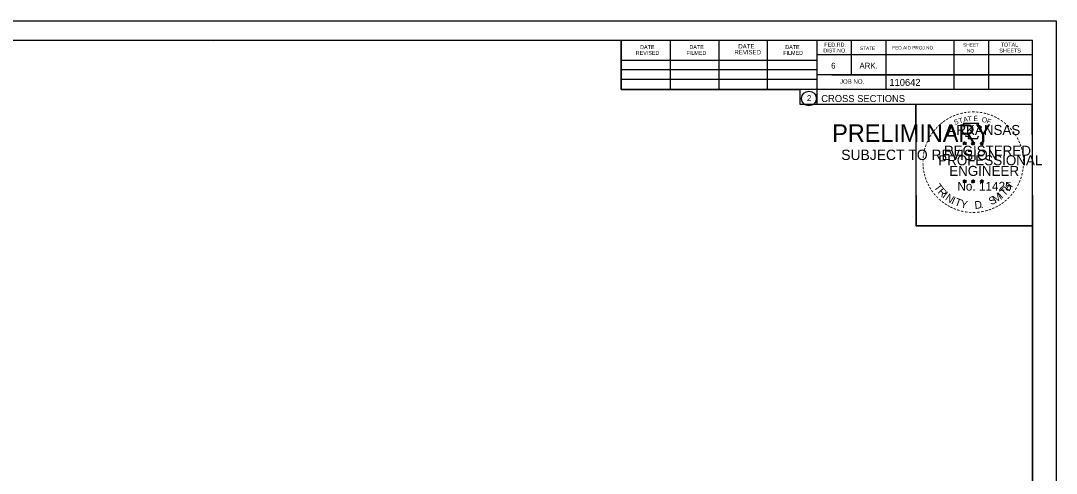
# Model space of a CAD drawing. Extents: x 1368503 to 1373085, y 379840 to 381833.
# Drawn here: x 1368628.9 to 1368836, y 380888.9 to 380979.4 of the extents above; entities that cross this region are included whole.
import ezdxf

# ---------------------------------------------------------------- set-up
doc = ezdxf.new("R2010")
doc.units = 0
for name, color, linetype in [('S_BRIDGE', 7, 'Continuous'), ('S_LANDSCAPING', 7, 'Continuous'), ('S_MISC_BOUNDARY_ANNOT', 7, 'Continuous'), ('S_PHOTO_NOTES', 7, 'Continuous')]:
    doc.layers.add(name, color=color, linetype=linetype)

msp = doc.modelspace()

# ---------------------------------------------------------------- linework, layer by layer
at = {"layer": 'S_BRIDGE'}
for p, q in [((1368515.06, 380975.5), (1368831.24, 380975.5)), ((1368667.58, 380975.24), (1368667.58, 380975.24)), ((1368667.58, 380975.24), (1368667.58, 380975.24)), ((1368748.98, 380965.62), (1368748.98, 380975.5)), ((1368758.84, 380965.62), (1368758.84, 380975.3)), ((1368768.6, 380965.62), (1368768.6, 380975.3)), ((1368778.28, 380965.62), (1368778.28, 380975.3)), ((1368788.14, 380975.5), (1368788.14, 380962.7)), ((1368794.98, 380975.5), (1368794.98, 380968.56)), ((1368801.92, 380975.5), (1368801.92, 380965.62)), ((1368815.5, 380975.5), (1368815.5, 380965.62)), ((1368822.44, 380975.5), (1368822.44, 380965.62)), ((1368831.24, 380770.04), (1368831.24, 380975.5)), ((1368831.24, 380972.56), (1368788.14, 380972.56)), ((1368831.24, 380972.58), (1368831.24, 380972.58)), ((1368748.98, 380971.48), (1368788.14, 380971.48)), ((1368748.98, 380969.62), (1368788.14, 380969.62)), ((1368748.98, 380965.62), (1368748.98, 380967.68)), ((1368748.98, 380967.68), (1368788.14, 380967.68)), ((1368831.24, 380968.56), (1368788.14, 380968.56)), ((1368791.1, 380968.56), (1368831.24, 380968.56)), ((1368831.24, 380965.62), (1368748.98, 380965.62)), ((1368788.14, 380962.7), (1368831.24, 380962.7))]:
    msp.add_line(p, q, dxfattribs=at)
msp.add_circle((1368786.53, 380963.84), 1.47, dxfattribs=at)
at = {"layer": 'S_LANDSCAPING'}
for p, q in [((1368817.67, 380955.21), (1368817.63, 380954.96)), ((1368817.67, 380954.85), (1368817.67, 380955.21)), ((1368817.67, 380955.21), (1368817.72, 380954.96)), ((1368819.34, 380955.21), (1368819.3, 380954.96)), ((1368819.34, 380954.85), (1368819.34, 380955.21)), ((1368819.34, 380955.21), (1368819.39, 380954.96)), ((1368821.11, 380955.2), (1368821.07, 380954.95)), ((1368821.11, 380954.83), (1368821.11, 380955.2)), ((1368821.11, 380955.2), (1368821.16, 380954.95)), ((1368817.32, 380954.96), (1368817.67, 380954.85)), ((1368817.32, 380954.96), (1368817.58, 380954.91)), ((1368817.32, 380954.96), (1368817.56, 380954.84)), ((1368817.46, 380954.55), (1368817.67, 380954.85)), ((1368817.46, 380954.55), (1368817.58, 380954.79)), ((1368817.46, 380954.55), (1368817.67, 380954.77)), ((1368818.02, 380954.96), (1368817.67, 380954.85)), ((1368817.89, 380954.55), (1368817.67, 380954.85)), ((1368817.89, 380954.55), (1368817.67, 380954.76)), ((1368818.02, 380954.96), (1368817.73, 380954.91)), ((1368817.89, 380954.55), (1368817.75, 380954.84)), ((1368818.02, 380954.96), (1368817.82, 380954.86)), ((1368818.99, 380954.96), (1368819.34, 380954.85)), ((1368818.99, 380954.96), (1368819.25, 380954.91)), ((1368818.99, 380954.96), (1368819.23, 380954.84)), ((1368819.13, 380954.55), (1368819.34, 380954.85)), ((1368819.13, 380954.55), (1368819.25, 380954.79)), ((1368819.13, 380954.55), (1368819.34, 380954.77)), ((1368819.69, 380954.96), (1368819.34, 380954.85)), ((1368819.56, 380954.55), (1368819.34, 380954.85)), ((1368819.56, 380954.55), (1368819.34, 380954.76)), ((1368819.69, 380954.96), (1368819.4, 380954.91)), ((1368819.56, 380954.55), (1368819.42, 380954.84)), ((1368819.69, 380954.96), (1368819.49, 380954.86)), ((1368820.76, 380954.95), (1368821.11, 380954.83)), ((1368820.76, 380954.95), (1368821.01, 380954.9)), ((1368820.76, 380954.95), (1368820.99, 380954.82)), ((1368820.89, 380954.54), (1368821.11, 380954.83)), ((1368820.89, 380954.54), (1368821.02, 380954.78)), ((1368820.89, 380954.54), (1368821.1, 380954.75)), ((1368821.32, 380954.54), (1368821.1, 380954.75)), ((1368821.45, 380954.95), (1368821.11, 380954.83)), ((1368821.32, 380954.54), (1368821.11, 380954.83)), ((1368821.45, 380954.95), (1368821.17, 380954.9)), ((1368821.32, 380954.54), (1368821.18, 380954.83)), ((1368821.45, 380954.95), (1368821.25, 380954.84)), ((1368817.32, 380947.38), (1368817.67, 380947.27)), ((1368817.32, 380947.38), (1368817.57, 380947.34)), ((1368817.32, 380947.38), (1368817.56, 380947.26)), ((1368817.45, 380946.98), (1368817.67, 380947.27)), ((1368817.45, 380946.98), (1368817.58, 380947.22)), ((1368817.45, 380946.98), (1368817.67, 380947.19)), ((1368817.67, 380947.64), (1368817.63, 380947.39)), ((1368817.67, 380947.27), (1368817.67, 380947.64)), ((1368817.67, 380947.64), (1368817.72, 380947.39)), ((1368818.02, 380947.38), (1368817.67, 380947.27)), ((1368817.88, 380946.98), (1368817.67, 380947.27)), ((1368817.88, 380946.98), (1368817.67, 380947.19)), ((1368818.02, 380947.38), (1368817.73, 380947.34)), ((1368817.88, 380946.98), (1368817.74, 380947.27)), ((1368818.02, 380947.38), (1368817.81, 380947.28)), ((1368818.99, 380947.38), (1368819.34, 380947.27)), ((1368818.99, 380947.38), (1368819.24, 380947.34)), ((1368818.99, 380947.38), (1368819.23, 380947.26)), ((1368819.12, 380946.98), (1368819.34, 380947.27)), ((1368819.12, 380946.98), (1368819.25, 380947.22)), ((1368819.12, 380946.98), (1368819.34, 380947.19)), ((1368819.34, 380947.64), (1368819.3, 380947.39)), ((1368819.34, 380947.27), (1368819.34, 380947.64)), ((1368819.34, 380947.64), (1368819.39, 380947.39)), ((1368819.68, 380947.38), (1368819.34, 380947.27)), ((1368819.55, 380946.98), (1368819.34, 380947.27)), ((1368819.55, 380946.98), (1368819.34, 380947.19)), ((1368819.68, 380947.38), (1368819.4, 380947.34)), ((1368819.55, 380946.98), (1368819.41, 380947.27)), ((1368819.68, 380947.38), (1368819.48, 380947.28)), ((1368820.76, 380947.37), (1368821.1, 380947.26)), ((1368820.76, 380947.37), (1368821.01, 380947.33)), ((1368820.76, 380947.37), (1368820.99, 380947.25)), ((1368820.89, 380946.97), (1368821.1, 380947.26)), ((1368820.89, 380946.97), (1368821.01, 380947.21)), ((1368820.89, 380946.97), (1368821.1, 380947.18)), ((1368821.1, 380947.63), (1368821.06, 380947.38)), ((1368821.1, 380947.26), (1368821.1, 380947.63)), ((1368821.1, 380947.63), (1368821.15, 380947.38)), ((1368821.45, 380947.37), (1368821.1, 380947.26)), ((1368821.32, 380946.97), (1368821.1, 380947.26)), ((1368821.32, 380946.97), (1368821.1, 380947.18)), ((1368821.45, 380947.37), (1368821.17, 380947.33)), ((1368821.32, 380946.97), (1368821.18, 380947.26)), ((1368821.45, 380947.37), (1368821.25, 380947.27))]:
    msp.add_line(p, q, dxfattribs=at)
for points in [[(1368817.36, 380958.84), (1368817.63, 380958.01)], [(1368820.88, 380957.91), (1368821.02, 380958.2), (1368820.33, 380958.17), (1368820.48, 380958.84), (1368817.36, 380958.84)], [(1368817.67, 380955.21), (1368817.89, 380954.55), (1368817.32, 380954.96), (1368818.02, 380954.96), (1368817.46, 380954.55), (1368817.67, 380955.21)], [(1368817.86, 380956.41), (1368817.86, 380956.33), (1368818.42, 380956.31), (1368818.37, 380955.83), (1368820.24, 380955.83), (1368820.44, 380956.37)], [(1368819.34, 380955.21), (1368819.56, 380954.55), (1368818.99, 380954.96), (1368819.69, 380954.96), (1368819.13, 380954.55), (1368819.34, 380955.21)], [(1368821.11, 380955.2), (1368821.32, 380954.54), (1368820.76, 380954.95), (1368821.45, 380954.95), (1368820.89, 380954.54), (1368821.11, 380955.2)], [(1368817.67, 380947.64), (1368817.88, 380946.98), (1368817.32, 380947.38), (1368818.02, 380947.38), (1368817.45, 380946.98), (1368817.67, 380947.64)], [(1368819.34, 380947.64), (1368819.55, 380946.98), (1368818.99, 380947.38), (1368819.68, 380947.38), (1368819.12, 380946.98), (1368819.34, 380947.64)], [(1368821.1, 380947.63), (1368821.32, 380946.97), (1368820.76, 380947.37), (1368821.45, 380947.37), (1368820.89, 380946.97), (1368821.1, 380947.63)]]:
    msp.add_lwpolyline(points, dxfattribs=at)
for centre, radius in [((1368817.67, 380954.85), 0.172), ((1368817.67, 380954.85), 0.145), ((1368817.67, 380954.85), 0.116), ((1368817.67, 380954.85), 0.0991), ((1368817.67, 380954.85), 0.0747), ((1368817.67, 380954.85), 0.0495), ((1368817.67, 380954.85), 0.0296), ((1368819.34, 380954.85), 0.172), ((1368819.34, 380954.85), 0.145), ((1368819.34, 380954.85), 0.116), ((1368819.34, 380954.85), 0.0991), ((1368819.34, 380954.85), 0.0747), ((1368819.34, 380954.85), 0.0495), ((1368819.34, 380954.85), 0.0296), ((1368821.11, 380954.83), 0.172), ((1368821.11, 380954.83), 0.145), ((1368821.11, 380954.83), 0.116), ((1368821.11, 380954.83), 0.0991), ((1368821.11, 380954.83), 0.0747), ((1368821.11, 380954.83), 0.0495), ((1368821.11, 380954.83), 0.0296), ((1368817.67, 380947.27), 0.172), ((1368817.67, 380947.27), 0.145), ((1368817.67, 380947.27), 0.116), ((1368817.67, 380947.27), 0.0991), ((1368817.67, 380947.27), 0.0747), ((1368817.67, 380947.27), 0.0495), ((1368817.67, 380947.27), 0.0296), ((1368819.34, 380947.27), 0.172), ((1368819.34, 380947.27), 0.145), ((1368819.34, 380947.27), 0.116), ((1368819.34, 380947.27), 0.0991), ((1368819.34, 380947.27), 0.0747), ((1368819.34, 380947.27), 0.0495), ((1368819.34, 380947.27), 0.0296), ((1368821.1, 380947.26), 0.172), ((1368821.1, 380947.26), 0.145), ((1368821.1, 380947.26), 0.116), ((1368821.1, 380947.26), 0.0991), ((1368821.1, 380947.26), 0.0747), ((1368821.1, 380947.26), 0.0495), ((1368821.1, 380947.26), 0.0296)]:
    msp.add_circle(centre, radius, dxfattribs=at)
at = {"layer": 'S_PHOTO_NOTES'}
for p, q in [((1368502.66, 380979.4), (1368835.99, 380979.4)), ((1368807.27, 380940.25), (1368807.27, 380940.25))]:
    msp.add_line(p, q, dxfattribs=at)
for points in [[(1368502.65, 380979.4), (1368835.99, 380979.4), (1368835.99, 380766.06), (1368502.65, 380766.06)], [(1368748.98, 380975.5), (1368748.98, 380965.62), (1368784.71, 380965.62), (1368784.71, 380962.7), (1368807.91, 380962.7), (1368807.91, 380938.37), (1368831.24, 380938.37), (1368831.24, 380770.04), (1368515.06, 380770.04), (1368515.06, 380975.5)], [(1368807.91, 380962.7), (1368831.12, 380962.7), (1368831.24, 380938.37), (1368808.03, 380938.37)]]:
    msp.add_lwpolyline(points, close=True, dxfattribs=at)

# ---------------------------------------------------------------- texts
at = {"layer": 'S_BRIDGE'}
for s, height, p in [('DATE', 0.782, (1368752.78, 380973.74)), ('DATE', 0.782, (1368762.64, 380973.74)), ('DATE', 0.879, (1368772.42, 380973.84)), ('DATE', 0.782, (1368781.8, 380973.74)), ('DIST.NO.', 0.782, (1368789.42, 380973.04)), ('FED.RD.', 0.782, (1368789.62, 380974.22)), ('STATE', 0.684, (1368796.74, 380973.54)), ('FED.AID PROJ.NO.', 0.684, (1368803.2, 380973.64)), ('SHEET', 0.684, (1368817.36, 380974.22)), ('NO.', 0.684, (1368818.14, 380973.04)), ('SHEETS', 0.782, (1368824.6, 380973.04)), ('TOTAL', 0.782, (1368824.88, 380974.22)), ('REVISED', 0.782, (1368751.9, 380972.56)), ('FILMED', 0.782, (1368762.06, 380972.56)), ('REVISED', 0.879, (1368771.64, 380972.66)), ('FILMED', 0.782, (1368781.4, 380972.56)), ('6', 1.17, (1368790.98, 380969.82)), ('ARK.', 1.172, (1368796.64, 380969.82)), ('JOB NO.', 0.879, (1368792.74, 380966.8)), ('110642', 1.4, (1368802.61, 380966.36)), ('2', 1.17, (1368786.14, 380963.35)), ('CROSS SECTIONS', 1.4, (1368789, 380963.13))]:
    msp.add_text(s, height=height, rotation=360, dxfattribs=at).set_placement(p)
at = {"layer": 'S_LANDSCAPING'}
for s, height, rotation, p in [('-', 1.6, 5.8968, (1368818.27, 380960.48)), ('-', 1.6, 0.1862, (1368819.04, 380960.55)), ('-', 1.6, 36.2317, (1368813.67, 380958.61)), ('-', 1.6, 34.0636, (1368814.25, 380959.01)), ('-', 1.6, 28.7918, (1368814.85, 380959.38)), ('-', 1.6, 24.3072, (1368815.48, 380959.69)), ('S', 1, 21.594, (1368815.72, 380958.51)), ('-', 1.6, 19.1761, (1368816.11, 380959.96)), ('T', 1, 16.4036, (1368816.63, 380958.84)), ('-', 1.6, 13.6301, (1368816.86, 380960.2)), ('A', 1, 11.2132, (1368817.46, 380959.1)), ('-', 1.6, 10.2193, (1368817.54, 380960.37)), ('T', 1, 6.0228, (1368818.31, 380959.26)), ('E', 1, 0.8323, (1368819.41, 380959.37)), ('-', 1.6, 357.743, (1368819.76, 380960.53)), ('-', 1.6, 352.1617, (1368820.51, 380960.48)), ('O', 1, 350.4515, (1368821.02, 380959.16)), ('-', 1.6, 347.2049, (1368821.23, 380960.36)), ('F', 1, 340.0707, (1368821.97, 380958.93)), ('-', 1.6, 342.3362, (1368821.86, 380960.21)), ('-', 1.6, 337.8551, (1368822.6, 380959.99)), ('-', 1.6, 334.1211, (1368823.23, 380959.72)), ('-', 1.6, 329.6409, (1368823.81, 380959.43)), ('-', 1.6, 325.8627, (1368824.45, 380959.07)), ('-', 1.6, 54.2325, (1368811.5, 380956.29)), ('-', 1.6, 50.6142, (1368811.91, 380956.85)), ('-', 1.6, 48.423, (1368812.31, 380957.34)), ('-', 1.6, 42.9622, (1368812.76, 380957.82)), ('-', 1.6, 38.9507, (1368813.19, 380958.23)), ('ARKANSAS', 2, 360, (1368814.22, 380956.55)), ('-', 1.6, 320.5297, (1368825.06, 380958.65)), ('-', 1.6, 315.5786, (1368825.66, 380958.16)), ('-', 1.6, 309.8797, (1368826.23, 380957.61)), ('-', 1.6, 306.6522, (1368826.75, 380957.01)), ('-', 1.6, 67.7743, (1368810.6, 380954.53)), ('-', 1.6, 62.8713, (1368810.86, 380955.14)), ('-', 1.6, 58.0706, (1368811.17, 380955.76)), ('-', 1.4, 303.6753, (1368827.24, 380956.44)), ('-', 1.6, 299.6684, (1368827.56, 380955.83)), ('-', 1.6, 294.6628, (1368827.88, 380955.22)), ('-', 1.6, 81.2013, (1368810.05, 380952.48)), ('-', 1.6, 75.461, (1368810.18, 380953.19)), ('-', 1.6, 72.3945, (1368810.38, 380953.9)), ('REGISTERED', 2, 360, (1368813.54, 380952.4)), ('DWB', 0.01, 360, (1368817.66, 380954.84)), ('DWB', 0.01, 360, (1368819.33, 380954.84)), ('DWB', 0.01, 360, (1368821.09, 380954.83)), ('-', 1.6, 290.5728, (1368828.14, 380954.64)), ('-', 1.6, 285.1233, (1368828.37, 380954.06)), ('-', 1.6, 280.5493, (1368828.57, 380953.32)), ('-', 1.6, 94.1959, (1368809.99, 380950.36)), ('-', 1.6, 89.0622, (1368809.95, 380951.08)), ('-', 1.6, 85.1863, (1368809.98, 380951.79)), ('PROFESSIONAL', 2, 360, (1368812.39, 380950.49)), ('-', 1.6, 276.5962, (1368828.74, 380952.55)), ('-', 1.6, 274.3301, (1368828.8, 380951.83)), ('-', 1.6, 269.9407, (1368828.83, 380951.2)), ('-', 1.6, 98.9479, (1368810.06, 380949.69)), ('-', 1.6, 101.7149, (1368810.19, 380948.96)), ('ENGINEER', 2, 360, (1368814.58, 380948.37)), ('-', 1.6, 255.7626, (1368828.63, 380949.2)), ('-', 1.6, 260.9953, (1368828.74, 380949.88)), ('-', 1.6, 263.5172, (1368828.81, 380950.53)), ('-', 1.6, 105.4578, (1368810.36, 380948.36)), ('-', 1.6, 109.0874, (1368810.57, 380947.73)), ('-', 1.6, 114.0643, (1368810.82, 380947.14)), ('-', 1.6, 115.7289, (1368811.13, 380946.52)), ('T', 1.54, 306.0406, (1368811.43, 380946.11)), ('No. 11425', 1.757, 360, (1368816.21, 380945.42)), ('DWB', 0.01, 360, (1368817.66, 380947.27)), ('DWB', 0.01, 360, (1368819.33, 380947.27)), ('DWB', 0.01, 360, (1368821.09, 380947.26)), ('H', 1.54, 54.6088, (1368826.55, 380945.15)), ('-', 1.6, 244.6197, (1368827.96, 380947.18)), ('-', 1.6, 247.8887, (1368828.23, 380947.81)), ('-', 1.6, 252.8681, (1368828.45, 380948.48)), ('-', 1.6, 120.4471, (1368811.49, 380945.93)), ('-', 1.6, 125.8934, (1368811.89, 380945.37)), ('-', 1.6, 130.7181, (1368812.35, 380944.82)), ('R', 1.54, 314.005, (1368812.19, 380945.06)), ('I', 1.54, 321.9694, (1368813.09, 380944.13)), ('N', 1.54, 326.5002, (1368813.66, 380943.66)), ('M', 1.54, 32.6563, (1368823.81, 380942.88)), ('I', 1.54, 42.1136, (1368825.1, 380943.73)), ('T', 1.54, 46.6444, (1368825.66, 380944.2)), ('-', 1.6, 231.2538, (1368826.74, 380945.21)), ('-', 1.6, 233.8452, (1368827.17, 380945.77)), ('-', 1.6, 239.0712, (1368827.57, 380946.43)), ('-', 1.6, 134.2238, (1368812.87, 380944.28)), ('-', 1.6, 138.9338, (1368813.39, 380943.81)), ('-', 1.6, 144.6463, (1368813.95, 380943.41)), ('-', 1.6, 148.0898, (1368814.51, 380943.03)), ('I', 1.54, 335.3603, (1368814.87, 380942.87)), ('T', 1.54, 339.8912, (1368815.53, 380942.55)), ('Y', 1.54, 347.8556, (1368816.74, 380942.1)), ('D', 1.54, 6.3969, (1368819.73, 380941.74)), ('S', 1.54, 26.9312, (1368822.97, 380942.47)), ('-', 1.6, 212.2491, (1368824.65, 380943.27)), ('-', 1.6, 215.7363, (1368825.19, 380943.66)), ('-', 1.6, 221.0851, (1368825.74, 380944.13)), ('-', 1.6, 225.7653, (1368826.26, 380944.64)), ('-', 1.6, 151.5704, (1368815.09, 380942.71)), ('-', 1.6, 154.6002, (1368815.61, 380942.46)), ('-', 1.6, 158.5612, (1368816.24, 380942.21)), ('-', 1.6, 162.7983, (1368816.92, 380942)), ('-', 1.6, 167.5555, (1368817.64, 380941.83)), ('-', 1.6, 173.1155, (1368818.41, 380941.72)), ('-', 1.6, 176.5183, (1368819.16, 380941.67)), ('-', 1.6, 181.5918, (1368819.9, 380941.69)), ('-', 1.6, 185.8167, (1368820.71, 380941.76)), ('-', 1.6, 191.2858, (1368821.45, 380941.9)), ('.', 1.54, 13.7642, (1368820.92, 380941.87)), ('-', 1.6, 195.4743, (1368822.18, 380942.09)), ('-', 1.6, 200.7184, (1368822.85, 380942.34)), ('-', 1.6, 204.2516, (1368823.47, 380942.61)), ('-', 1.6, 207.3568, (1368824.1, 380942.93))]:
    msp.add_text(s, height=height, rotation=rotation, dxfattribs=at).set_placement(p)
at = {"layer": 'S_MISC_BOUNDARY_ANNOT'}
for s, height, p in [('PRELIMINARY', 3.5, (1368791.19, 380955.17)), ('DWB', 0.01, (1368791.94, 380957.01)), ('SUBJECT TO REVISION', 2.0751, (1368793, 380951.54))]:
    msp.add_text(s, height=height, rotation=360, dxfattribs=at).set_placement(p)

doc.saveas('drawing.dxf')
